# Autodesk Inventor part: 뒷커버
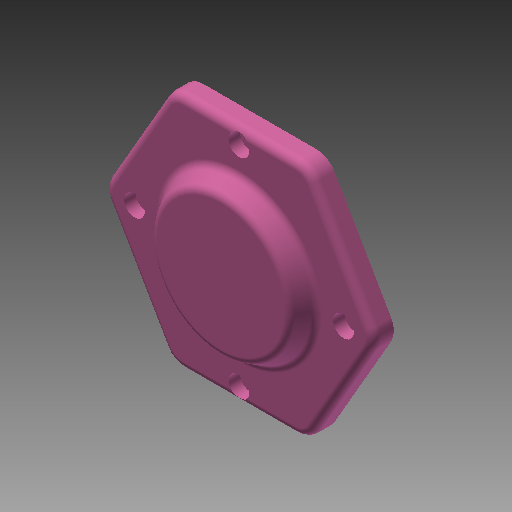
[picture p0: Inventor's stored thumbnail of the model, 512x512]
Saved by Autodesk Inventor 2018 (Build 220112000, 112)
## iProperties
Created: 2013-02
Part Number: 뒷커버
Document SubType Name: Modeling
Density: 1 g/cm^3
Material: 일반
Appearance: 분홍색
Author: 한국산업디자인학원[gmhk.co.kr]
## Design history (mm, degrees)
sketch "스케치1" dims "d37" = 105
  geometry: L1 (50.191, -4)-(28.559, -41.466); L2 (21.631, -45.466)-(-21.631, -45.466); L3 (-28.559, -41.466)-(-50.191, -4); L4 (-50.191, 4)-(-28.559, 41.466); L5 (-21.631, 45.466)-(21.631, 45.466); L6 (28.559, 41.466)-(50.191, 4); C1 r 30 at (0, 0); A1 r 8 centre (-21.631, 37.466) between (-21.631, 45.466) and (-28.559, 41.466); A2 r 8 centre (21.631, 37.466) between (28.559, 41.466) and (21.631, 45.466); A3 r 8 centre (43.262, 0) between (50.191, -4) and (50.191, 4); A4 r 8 centre (21.631, -37.466) between (21.631, -45.466) and (28.559, -41.466); A5 r 8 centre (-21.631, -37.466) between (-28.559, -41.466) and (-21.631, -45.466); A6 r 8 centre (-43.262, 0) between (-50.191, 4) and (-50.191, -4); 9 further points
  constraints: 12 end point, 12 point on circle, 12 point on line, 12 tangent, 7 centre point, 5 equal radius, 3 coincident, 1 horizontal, 1 horizontal alignment, 15 other
  dimensions: "d39" = 60 diameter of C1; "d40" = 8 radius of A1
extrude "돌출1" new body sketch "스케치1" distance "d0" = 8; taper "d1" = 0 deg
sketch "스케치2"
  geometry: C1 r 30 at (0, 0); 1 further point
  constraints: 1 centre point, 1 coincident
  dimensions: "d2" = 60 diameter of C1
extrude "돌출2" join sketch "스케치2" distance "d3" = 7; taper "d4" = -30 deg
sketch "스케치3"
  geometry: C1 r 30 at (0, 0) reference; A1 r 40 centre (0, 0) between (0, 40) and (-40, 0); 2 further points
  constraints: 4 point on circle, 2 horizontal alignment, 2 vertical alignment, 1 centre point, 1 coincident
  dimensions: "d47" = 80 diameter of A1
hole "구멍2" sketch "스케치3" at (0, 40), (-40, 0), (0, -40), (40, 0) diameter "d14" = 4.5; stored, may be unused: countersink angle "d18" = 90 deg, drill point angle "d20" = 118 deg; dims "d15" = 6, "d16" = 8, "d17" = 4.4, "d19" = 20
extrude "돌출3" join sketch "스케치1" distance "d21" = 12; taper "d22" = 0 deg
hole "구멍3" diameter "d25" = 30; stored, may be unused: countersink angle "d29" = 90 deg, drill point angle "d31" = 0 deg; dims "d26" = 6, "d27" = 42, "d28" = 13, "d30" = 16, "d50" = 10, "d51" = 10
fillet "모깎기1" dims "d32" = 3, "d33" = 1
chamfer "모따기1" distance "d34" = 1; stored, may be unused: second distance "d35" = 2, angle "d36" = 45 deg
chamfer "모따기2" distance "d43" = 1; stored, may be unused: second distance "d44" = 2, angle "d45" = 45 deg
fillet "모깎기2" dims "d46" = 3
node "솔리드1"
